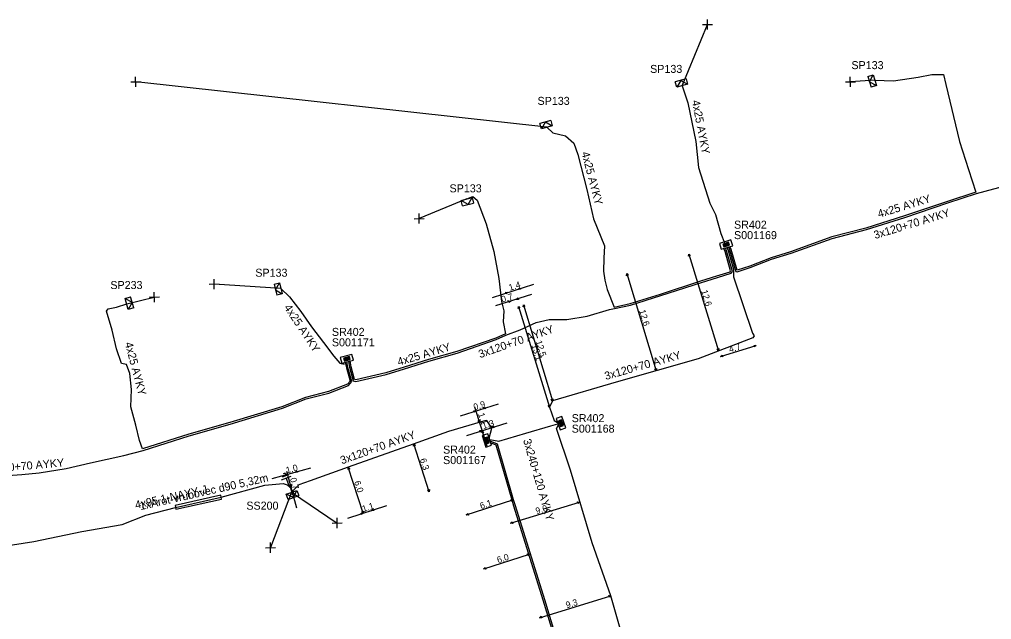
# Model space of a CAD drawing. Extents: x -762504 to -761250, y -1152974 to -1152253.
# Drawn here: x -761447.4 to -761326.7, y -1152367.8 to -1152293.3 of the extents above; entities that cross this region are included whole.
import ezdxf

# ---------------------------------------------------------------- set-up
doc = ezdxf.new("R2010")
doc.units = 0
for name, color, linetype in [('Vrstva 15', 7, 'Continuous'), ('Vrstva 20', 7, 'Continuous'), ('Vrstva 21', 7, 'Continuous'), ('Vrstva 28', 7, 'Continuous'), ('Vrstva 29', 7, 'Continuous'), ('Vrstva 30', 7, 'Continuous'), ('Vrstva 31', 7, 'Continuous'), ('Vrstva 33', 7, 'Continuous'), ('Vrstva 34', 7, 'Continuous'), ('Vrstva 40', 7, 'Continuous'), ('Vrstva 5', 7, 'Continuous'), ('Vrstva 59', 7, 'Continuous'), ('Vrstva 6', 7, 'Continuous')]:
    doc.layers.add(name, color=color, linetype=linetype)

msp = doc.modelspace()

# ---------------------------------------------------------------- linework, layer by layer
at = {"layer": 'Vrstva 15'}
for points in [[(-761414.767, -1152350.065), (-761414.027, -1152349.796)], [(-761414.639, -1152349.683), (-761414.514, -1152349.638)], [(-761414.514, -1152349.638), (-761414.394, -1152349.594)], [(-761414.888, -1152350.439), (-761413.713, -1152350.011)], [(-761413.873, -1152351.4), (-761414.301, -1152350.225)]]:
    msp.add_lwpolyline(points, dxfattribs=at)
at = {"layer": 'Vrstva 20'}
msp.add_lwpolyline([(-761422.44, -1152352.36), (-761428.12, -1152353.64), (-761428.01, -1152354.12), (-761422.33, -1152352.84)], close=True, dxfattribs=at)
at = {"layer": 'Vrstva 28'}
for points in [[(-761359.083, -1152320.657), (-761360.517, -1152321.096)], [(-761359.384, -1152320.947), (-761360.095, -1152321.165)], [(-761359.273, -1152321.308), (-761359.384, -1152320.947)], [(-761358.864, -1152321.375), (-761359.083, -1152320.657)], [(-761360.517, -1152321.096), (-761360.298, -1152321.813)], [(-761360.298, -1152321.813), (-761358.864, -1152321.375)], [(-761360.095, -1152321.165), (-761359.985, -1152321.526)], [(-761359.415, -1152321.006), (-761360.036, -1152321.196)], [(-761360.036, -1152321.196), (-761359.953, -1152321.467)], [(-761359.985, -1152321.526), (-761359.273, -1152321.308)], [(-761359.446, -1152321.065), (-761359.977, -1152321.227)], [(-761359.977, -1152321.227), (-761359.922, -1152321.408)], [(-761359.953, -1152321.467), (-761359.332, -1152321.277)], [(-761359.922, -1152321.408), (-761359.391, -1152321.246)], [(-761359.478, -1152321.124), (-761359.918, -1152321.259)], [(-761359.918, -1152321.259), (-761359.891, -1152321.349)], [(-761359.891, -1152321.349), (-761359.45, -1152321.214)], [(-761359.503, -1152321.181), (-761359.865, -1152321.292)], [(-761359.45, -1152321.214), (-761359.478, -1152321.124)], [(-761359.391, -1152321.246), (-761359.446, -1152321.065)], [(-761359.332, -1152321.277), (-761359.415, -1152321.006)], [(-761406.151, -1152334.865), (-761407.6, -1152335.254)], [(-761407.6, -1152335.254), (-761407.406, -1152335.978)], [(-761406.461, -1152335.144), (-761407.18, -1152335.337)], [(-761407.18, -1152335.337), (-761407.082, -1152335.702)], [(-761406.495, -1152335.202), (-761407.122, -1152335.37)], [(-761407.122, -1152335.37), (-761407.049, -1152335.644)], [(-761406.528, -1152335.26), (-761407.064, -1152335.404)], [(-761407.064, -1152335.404), (-761407.015, -1152335.586)], [(-761406.561, -1152335.318), (-761407.006, -1152335.437)], [(-761406.982, -1152335.528), (-761406.537, -1152335.409)], [(-761406.589, -1152335.374), (-761406.954, -1152335.472)], [(-761406.537, -1152335.409), (-761406.561, -1152335.318)], [(-761406.479, -1152335.442), (-761406.528, -1152335.26)], [(-761406.421, -1152335.476), (-761406.495, -1152335.202)], [(-761406.363, -1152335.509), (-761406.461, -1152335.144)], [(-761405.957, -1152335.59), (-761406.151, -1152334.865)], [(-761407.406, -1152335.978), (-761405.957, -1152335.59)], [(-761407.082, -1152335.702), (-761406.363, -1152335.509)], [(-761407.049, -1152335.644), (-761406.421, -1152335.476)], [(-761407.015, -1152335.586), (-761406.479, -1152335.442)], [(-761407.006, -1152335.437), (-761406.982, -1152335.528)], [(-761380.079, -1152342.586), (-761380.788, -1152342.83)], [(-761379.591, -1152344.004), (-761380.079, -1152342.586)], [(-761380.788, -1152342.83), (-761380.3, -1152344.248)], [(-761380.133, -1152343.01), (-761380.49, -1152343.133)], [(-761380.49, -1152343.133), (-761380.248, -1152343.837)], [(-761380.162, -1152343.07), (-761380.43, -1152343.162)], [(-761380.43, -1152343.162), (-761380.219, -1152343.777)], [(-761380.192, -1152343.13), (-761380.37, -1152343.192)], [(-761380.37, -1152343.192), (-761380.189, -1152343.717)], [(-761380.221, -1152343.19), (-761380.31, -1152343.221)], [(-761380.31, -1152343.221), (-761380.16, -1152343.657)], [(-761380.129, -1152343.602), (-761380.252, -1152343.245)], [(-761380.248, -1152343.837), (-761379.891, -1152343.714)], [(-761380.071, -1152343.626), (-761380.221, -1152343.19)], [(-761380.219, -1152343.777), (-761379.951, -1152343.684)], [(-761380.011, -1152343.655), (-761380.192, -1152343.13)], [(-761380.189, -1152343.717), (-761380.011, -1152343.655)], [(-761379.951, -1152343.684), (-761380.162, -1152343.07)], [(-761380.16, -1152343.657), (-761380.071, -1152343.626)], [(-761379.891, -1152343.714), (-761380.133, -1152343.01)], [(-761389.255, -1152344.734), (-761389.973, -1152344.953)], [(-761389.973, -1152344.953), (-761389.534, -1152346.388)], [(-761388.817, -1152346.168), (-761389.255, -1152344.734)], [(-761380.3, -1152344.248), (-761379.591, -1152344.004)], [(-761389.322, -1152345.143), (-761389.683, -1152345.254)], [(-761389.683, -1152345.254), (-761389.465, -1152345.965)], [(-761389.353, -1152345.202), (-761389.624, -1152345.285)], [(-761389.624, -1152345.285), (-761389.434, -1152345.906)], [(-761389.384, -1152345.261), (-761389.565, -1152345.316)], [(-761389.565, -1152345.316), (-761389.403, -1152345.847)], [(-761389.534, -1152346.388), (-761388.817, -1152346.168)], [(-761389.416, -1152345.32), (-761389.506, -1152345.348)], [(-761389.506, -1152345.348), (-761389.371, -1152345.788)], [(-761389.465, -1152345.965), (-761389.104, -1152345.855)], [(-761389.449, -1152345.373), (-761389.338, -1152345.735)], [(-761389.434, -1152345.906), (-761389.163, -1152345.823)], [(-761389.281, -1152345.761), (-761389.416, -1152345.32)], [(-761389.403, -1152345.847), (-761389.222, -1152345.792)], [(-761389.222, -1152345.792), (-761389.384, -1152345.261)], [(-761389.371, -1152345.788), (-761389.281, -1152345.761)], [(-761389.163, -1152345.823), (-761389.353, -1152345.202)], [(-761389.104, -1152345.855), (-761389.322, -1152345.143)]]:
    msp.add_lwpolyline(points, dxfattribs=at)
at = {"layer": 'Vrstva 31'}
for points in [[(-761342.075, -1152300.333), (-761341.406, -1152300.128), (-761340.997, -1152301.467), (-761341.666, -1152301.671)], [(-761342.075, -1152300.333), (-761341.666, -1152301.671)], [(-761341.871, -1152301.002), (-761341.406, -1152300.128)], [(-761364.642, -1152300.642), (-761365.995, -1152301.004)], [(-761364.642, -1152300.642), (-761364.461, -1152301.318), (-761365.813, -1152301.68), (-761365.995, -1152301.004)], [(-761365.318, -1152300.823), (-761365.813, -1152301.68)], [(-761365.318, -1152300.823), (-761364.461, -1152301.318)], [(-761341.871, -1152301.002), (-761340.997, -1152301.467)], [(-761381.457, -1152305.793), (-761382.803, -1152306.179)], [(-761381.457, -1152305.793), (-761381.264, -1152306.466), (-761382.61, -1152306.852), (-761382.803, -1152306.179)], [(-761382.13, -1152305.986), (-761382.61, -1152306.852)], [(-761382.13, -1152305.986), (-761381.264, -1152306.466)], [(-761392.403, -1152316.41), (-761392.572, -1152315.73), (-761391.213, -1152315.392), (-761391.044, -1152316.071)], [(-761391.723, -1152316.24), (-761392.572, -1152315.73)], [(-761392.403, -1152316.41), (-761391.044, -1152316.071)], [(-761391.723, -1152316.24), (-761391.213, -1152315.392)], [(-761415.811, -1152326.153), (-761415.129, -1152325.995), (-761414.814, -1152327.359), (-761415.496, -1152327.517)], [(-761415.811, -1152326.153), (-761415.496, -1152327.517)], [(-761415.653, -1152326.835), (-761415.129, -1152325.995)], [(-761415.653, -1152326.835), (-761414.814, -1152327.359)], [(-761433.253, -1152329.083), (-761433.926, -1152329.276), (-761434.312, -1152327.93), (-761433.639, -1152327.737)], [(-761433.446, -1152328.41), (-761434.312, -1152327.93)], [(-761433.253, -1152329.083), (-761433.639, -1152327.737)], [(-761433.446, -1152328.41), (-761433.926, -1152329.276)], [(-761414.071, -1152352.899), (-761414.31, -1152352.241), (-761412.995, -1152351.762), (-761412.755, -1152352.42)], [(-761413.413, -1152352.659), (-761414.31, -1152352.241)], [(-761413.413, -1152352.659), (-761412.995, -1152351.762)], [(-761414.071, -1152352.899), (-761412.755, -1152352.42)]]:
    msp.add_lwpolyline(points, dxfattribs=at)
at = {"layer": 'Vrstva 34'}
for points in [[(-761362.625, -1152293.891), (-761361.375, -1152293.869)], [(-761361.989, -1152294.505), (-761362.011, -1152293.255)], [(-761432.989, -1152301.625), (-761433.011, -1152300.375)], [(-761344.239, -1152301.625), (-761344.261, -1152300.375)], [(-761433.625, -1152301.011), (-761432.375, -1152300.989)], [(-761344.875, -1152301.011), (-761343.625, -1152300.989)], [(-761398.435, -1152318.011), (-761397.185, -1152317.989)], [(-761397.799, -1152318.625), (-761397.821, -1152317.375)], [(-761423.239, -1152326.755), (-761423.261, -1152325.505)], [(-761423.875, -1152326.141), (-761422.625, -1152326.119)], [(-761431.315, -1152327.761), (-761430.065, -1152327.739)], [(-761430.679, -1152328.375), (-761430.701, -1152327.125)], [(-761408.615, -1152355.831), (-761407.365, -1152355.809)], [(-761407.979, -1152356.445), (-761408.001, -1152355.195)], [(-761416.259, -1152359.505), (-761416.281, -1152358.255)], [(-761416.895, -1152358.891), (-761415.645, -1152358.869)]]:
    msp.add_lwpolyline(points, dxfattribs=at)
at = {"layer": 'Vrstva 40'}
for points in [[(-761364.331, -1152322.418), (-761364.154, -1152322.622), (-761364.353, -1152322.686)], [(-761372.011, -1152324.838), (-761371.838, -1152325.045), (-761372.038, -1152325.106)], [(-761385.492, -1152326.76), (-761385.288, -1152326.584), (-761385.224, -1152326.783)], [(-761386.778, -1152327.179), (-761386.982, -1152327.356), (-761387.046, -1152327.157)], [(-761385.752, -1152328.04), (-761385.548, -1152327.864), (-761385.483, -1152328.063)], [(-761386.427, -1152328.249), (-761386.631, -1152328.425), (-761386.696, -1152328.226)], [(-761385.481, -1152328.908), (-761385.305, -1152329.112), (-761385.503, -1152329.176)], [(-761384.85, -1152328.708), (-761384.678, -1152328.915), (-761384.877, -1152328.976)], [(-761360.62, -1152334.422), (-761360.796, -1152334.218), (-761360.597, -1152334.154)], [(-761355.938, -1152333.77), (-761356.142, -1152333.946), (-761356.206, -1152333.747)], [(-761360.393, -1152335.151), (-761360.189, -1152334.974), (-761360.124, -1152335.173)], [(-761368.369, -1152336.903), (-761368.542, -1152336.696), (-761368.342, -1152336.634)], [(-761389.873, -1152341.611), (-761389.669, -1152341.434), (-761389.604, -1152341.633)], [(-761381.599, -1152341.432), (-761381.776, -1152341.228), (-761381.577, -1152341.164)], [(-761381.239, -1152340.662), (-761381.412, -1152340.455), (-761381.212, -1152340.394)], [(-761390.747, -1152341.889), (-761390.951, -1152342.065), (-761391.016, -1152341.866)], [(-761390.29, -1152343.323), (-761390.466, -1152343.119), (-761390.267, -1152343.054)], [(-761388.782, -1152343.961), (-761388.578, -1152343.784), (-761388.513, -1152343.983)], [(-761389.988, -1152344.34), (-761390.192, -1152344.516), (-761390.256, -1152344.317)], [(-761389.961, -1152344.358), (-761389.785, -1152344.562), (-761389.983, -1152344.627)], [(-761398.481, -1152345.987), (-761398.305, -1152346.191), (-761398.504, -1152346.256)], [(-761414.127, -1152349.75), (-761414.337, -1152349.919), (-761414.395, -1152349.718)], [(-761413.182, -1152349.49), (-761412.972, -1152349.321), (-761412.914, -1152349.522)], [(-761406.601, -1152348.897), (-761406.424, -1152349.102), (-761406.623, -1152349.166)], [(-761413.699, -1152351.353), (-761413.868, -1152351.143), (-761413.667, -1152351.085)], [(-761413.51, -1152352.038), (-761413.341, -1152352.248), (-761413.542, -1152352.305)], [(-761396.549, -1152351.943), (-761396.726, -1152351.738), (-761396.527, -1152351.674)], [(-761386.168, -1152352.949), (-761386.372, -1152353.125), (-761386.436, -1152352.927)], [(-761377.867, -1152353.21), (-761378.071, -1152353.386), (-761378.136, -1152353.187)], [(-761404.748, -1152354.599), (-761404.952, -1152354.775), (-761405.016, -1152354.577)], [(-761404.749, -1152354.602), (-761404.926, -1152354.398), (-761404.727, -1152354.334)], [(-761403.702, -1152354.261), (-761403.498, -1152354.084), (-761403.434, -1152354.283)], [(-761391.963, -1152354.821), (-761391.758, -1152354.644), (-761391.694, -1152354.843)], [(-761386.452, -1152355.851), (-761386.248, -1152355.674), (-761386.184, -1152355.873)], [(-761384.087, -1152359.69), (-761384.292, -1152359.866), (-761384.356, -1152359.667)], [(-761389.793, -1152361.531), (-761389.588, -1152361.354), (-761389.524, -1152361.553)], [(-761373.978, -1152364.859), (-761374.182, -1152365.036), (-761374.246, -1152364.837)], [(-761382.842, -1152367.58), (-761382.638, -1152367.404), (-761382.573, -1152367.603)]]:
    msp.add_lwpolyline(points, close=True, dxfattribs=at)
for points in [[(-761364.33, -1152322.42), (-761360.62, -1152334.42)], [(-761372.01, -1152324.84), (-761368.37, -1152336.9)], [(-761388.68, -1152327.79), (-761383.58, -1152326.16)], [(-761383.84, -1152327.44), (-761388.34, -1152328.84)], [(-761385.48, -1152328.91), (-761381.6, -1152341.43)], [(-761384.85, -1152328.71), (-761381.24, -1152340.66)], [(-761360.39, -1152335.15), (-761355.94, -1152333.77)], [(-761392.65, -1152342.5), (-761387.96, -1152341)], [(-761389.35, -1152346.27), (-761390.9, -1152341.41)], [(-761391.9, -1152344.93), (-761386.87, -1152343.37)], [(-761396.55, -1152351.94), (-761398.48, -1152345.99)], [(-761416.06, -1152350.28), (-761411.25, -1152348.97)], [(-761412.98, -1152353.97), (-761414.22, -1152349.42)], [(-761404.75, -1152354.6), (-761406.6, -1152348.9)], [(-761391.96, -1152354.82), (-761386.17, -1152352.95)], [(-761386.45, -1152355.85), (-761377.87, -1152353.21)], [(-761406.65, -1152355.22), (-761401.8, -1152353.64)], [(-761389.79, -1152361.53), (-761384.09, -1152359.69)], [(-761382.84, -1152367.58), (-761373.98, -1152364.86)]]:
    msp.add_lwpolyline(points, dxfattribs=at)
at = {"layer": 'Vrstva 5'}
for points in [[(-761341.2, -1152300.8), (-761338.88, -1152300.9), (-761335.82, -1152300.44), (-761334.13, -1152300.1), (-761332.68, -1152300.11), (-761332.41, -1152301.32), (-761330.71, -1152308.4), (-761329.6, -1152311.91), (-761328.66, -1152314.71), (-761332.2, -1152315.86), (-761337.55, -1152317.66), (-761342.33, -1152319.17), (-761346.56, -1152320.26), (-761351.68, -1152322.11), (-761354.1, -1152322.86), (-761356.75, -1152323.91), (-761358.32, -1152324.41), (-761359.06, -1152321.83), (-761359.21, -1152321.45)], [(-761365.14, -1152301.5), (-761364.44, -1152303.61), (-761363.46, -1152308.43), (-761363.12, -1152311.66), (-761361.71, -1152316.09), (-761361, -1152317.5), (-761360.32, -1152319.86), (-761359.89, -1152320.99)], [(-761381.94, -1152306.66), (-761381.21, -1152307.36), (-761379.64, -1152307.7), (-761378.61, -1152308.62), (-761378.09, -1152310.04), (-761376.96, -1152314.37), (-761376.15, -1152318.03), (-761374.8, -1152321.38), (-761374.86, -1152322.92), (-761374.93, -1152324.53), (-761374.74, -1152325.63), (-761374.45, -1152326.8), (-761373.59, -1152328.99), (-761371.61, -1152328.56), (-761367.83, -1152327.38), (-761362.82, -1152325.75), (-761360.82, -1152325.12), (-761359.2, -1152324.6), (-761359.13, -1152324.47), (-761359.82, -1152322.09), (-761359.95, -1152321.73)], [(-761359.39, -1152321.52), (-761359.25, -1152321.9), (-761358.48, -1152324.57), (-761358.31, -1152324.62), (-761356.69, -1152324.09), (-761354.04, -1152323.04), (-761351.62, -1152322.3), (-761346.5, -1152320.46), (-761342.27, -1152319.37), (-761337.49, -1152317.85), (-761332.14, -1152316.05), (-761328.6, -1152314.9), (-761324.75, -1152313.83), (-761321.73, -1152312.99), (-761318.49, -1152312), (-761317.09, -1152311.55), (-761314.13, -1152310.74), (-761310.4, -1152309.51), (-761310.19, -1152308.81), (-761310.75, -1152307.52), (-761310.97, -1152306.6)], [(-761391.89, -1152315.56), (-761391.13, -1152315.27), (-761390.59, -1152315.71), (-761389.5, -1152318.67), (-761388.54, -1152322.07), (-761387.92, -1152325.45), (-761387.56, -1152328.31), (-761387.29, -1152329.46), (-761387.39, -1152330.81), (-761387.1, -1152332.3), (-761388.3, -1152332.85), (-761393.14, -1152334.51), (-761396.65, -1152335.51), (-761399.68, -1152336.47), (-761401.95, -1152337.16), (-761405.66, -1152338.04), (-761405.82, -1152337.99), (-761406.25, -1152336.4), (-761406.39, -1152335.69)], [(-761406.58, -1152335.75), (-761406.44, -1152336.45), (-761405.99, -1152338.15), (-761405.66, -1152338.24), (-761401.89, -1152337.36), (-761399.62, -1152336.66), (-761396.59, -1152335.71), (-761393.08, -1152334.71), (-761388.22, -1152333.03), (-761387.04, -1152332.49), (-761385.26, -1152331.81), (-761383.26, -1152330.92), (-761381.67, -1152330.52), (-761379.47, -1152330.55), (-761376.93, -1152330.12), (-761374.15, -1152329.28), (-761373.53, -1152329.18), (-761371.56, -1152328.76), (-761367.77, -1152327.57), (-761362.76, -1152325.94), (-761360.76, -1152325.31), (-761359.05, -1152324.77), (-761358.89, -1152324.58), (-761359.63, -1152322.02), (-761359.77, -1152321.66)], [(-761359.58, -1152321.59), (-761359.44, -1152321.96), (-761358.77, -1152324.28), (-761358.76, -1152325.22), (-761356.41, -1152332.22), (-761356.21, -1152332.58), (-761356.37, -1152332.81), (-761363.16, -1152335.41), (-761373.34, -1152338.32), (-761381.24, -1152340.66), (-761381.6, -1152341.43), (-761381.05, -1152343.08), (-761380.61, -1152343.34)], [(-761414.97, -1152326.68), (-761413.92, -1152327.7), (-761412.48, -1152329.54), (-761411.16, -1152331.46), (-761409.69, -1152333.39), (-761408.39, -1152335.1), (-761407.66, -1152335.98), (-761407.13, -1152336.09), (-761407.17, -1152335.91)], [(-761406.97, -1152335.87), (-761406.83, -1152336.54), (-761406.39, -1152338.18), (-761406.7, -1152338.59), (-761409.06, -1152339.5), (-761411.9, -1152340.22), (-761414.85, -1152341.38), (-761421.32, -1152343.35), (-761426.42, -1152344.79), (-761432.15, -1152346.62), (-761432.53, -1152345.57), (-761432.99, -1152343.67), (-761433.6, -1152341.4), (-761433.53, -1152339.23), (-761433.73, -1152337.26), (-761434.13, -1152336.13), (-761434.77, -1152336.02), (-761435.4, -1152334.2), (-761435.94, -1152331.87), (-761436.62, -1152329.49), (-761436.41, -1152329.23), (-761435.37, -1152329.02), (-761434.12, -1152328.6)], [(-761450.14, -1152349.98), (-761447.16, -1152349.78), (-761445, -1152349.59), (-761441.65, -1152349.04), (-761438.6, -1152348.33), (-761434.47, -1152347.42), (-761432.09, -1152346.81), (-761426.36, -1152344.99), (-761421.26, -1152343.55), (-761414.79, -1152341.56), (-761411.84, -1152340.41), (-761409, -1152339.69), (-761406.58, -1152338.75), (-761406.17, -1152338.22), (-761406.64, -1152336.49), (-761406.78, -1152335.81)], [(-761389.11, -1152345.26), (-761388.78, -1152344.03), (-761389.4, -1152343.08), (-761389.83, -1152343.15), (-761394.15, -1152344.46), (-761398.56, -1152346.01), (-761406.6, -1152348.9), (-761411.32, -1152350.6), (-761412.74, -1152351.09), (-761413.65, -1152352)], [(-761389.04, -1152345.45), (-761387.89, -1152345.67), (-761384.57, -1152344.65), (-761381.43, -1152343.76), (-761380.57, -1152343.5)], [(-761372.68, -1152369.52), (-761373.98, -1152364.86), (-761376.31, -1152358.28), (-761379, -1152349.26), (-761380.75, -1152344.09), (-761380.51, -1152343.63)], [(-761379.03, -1152375.78), (-761382.2, -1152365.35), (-761385.85, -1152353.67), (-761386.07, -1152352.92), (-761388.07, -1152346.03), (-761388.99, -1152345.64)], [(-761379.23, -1152375.84), (-761382.4, -1152365.41), (-761386.05, -1152353.73), (-761386.27, -1152352.98), (-761388.25, -1152346.15), (-761388.93, -1152345.85)], [(-761451.55, -1152359.02), (-761445.67, -1152358.12), (-761439.7, -1152356.89), (-761434.68, -1152356), (-761431.74, -1152354.83), (-761428.06, -1152353.88), (-761422.38, -1152352.6), (-761416.97, -1152351.1), (-761414.67, -1152350.93), (-761414.2, -1152351.06), (-761413.77, -1152351.45), (-761413.65, -1152352)]]:
    msp.add_lwpolyline(points, dxfattribs=at)
at = {"layer": 'Vrstva 59'}
for points in [[(-761365.14, -1152301.5), (-761362, -1152293.88)], [(-761381.94, -1152306.66), (-761433, -1152301)], [(-761341.2, -1152300.8), (-761344.25, -1152301)], [(-761391.89, -1152315.56), (-761397.81, -1152318)], [(-761414.97, -1152326.68), (-761423.25, -1152326.13)], [(-761434.12, -1152328.6), (-761430.69, -1152327.75)], [(-761413.65, -1152352), (-761416.27, -1152358.88)], [(-761413.65, -1152352), (-761407.99, -1152355.82)]]:
    msp.add_lwpolyline(points, dxfattribs=at)

# ---------------------------------------------------------------- texts
at = {"layer": 'Vrstva 21'}
msp.add_text('1xArot-vrubovec d90 5,32m', height=0.99428, rotation=12.69958, dxfattribs=at).set_placement((-761432.39, -1152354.22))
at = {"layer": 'Vrstva 29'}
for s, p in [('S001169', (-761358.7, -1152320.55)), ('S001171', (-761408.64, -1152333.87)), ('S001168', (-761378.86, -1152344.59)), ('S001167', (-761394.83, -1152348.5))]:
    msp.add_text(s, height=0.9943, dxfattribs=at).set_placement(p)
at = {"layer": 'Vrstva 30'}
for p in [(-761358.7, -1152319.25), (-761408.64, -1152332.57), (-761378.86, -1152343.29), (-761394.83, -1152347.2)]:
    msp.add_text('SR402', height=0.9943, dxfattribs=at).set_placement(p)
at = {"layer": 'Vrstva 33'}
for s, p in [('SP133', (-761369.12, -1152299.9)), ('SP133', (-761344.12, -1152299.43)), ('SP133', (-761383.1, -1152303.87)), ('SP133', (-761394.03, -1152314.74)), ('SP133', (-761418.15, -1152325.22)), ('SP233', (-761436.15, -1152326.75)), ('SS200', (-761419.26, -1152354.16))]:
    msp.add_text(s, height=0.9943, dxfattribs=at).set_placement(p)
at = {"layer": 'Vrstva 40'}
for s, rotation, p in [('1,4', 17.73493, (-761386.54, -1152326.97)), ('12,6', 287.18504, (-761362.79, -1152326.99)), ('0,7', 17.2057, (-761387.48, -1152328.45)), ('12,6', 286.79207, (-761370.5, -1152329.44)), ('13,1', 287.21377, (-761383.86, -1152333.74)), ('12,5', 286.7921, (-761383.35, -1152333.26)), ('4,7', 17.18324, (-761359.21, -1152334.66)), ('0,9', 17.66268, (-761390.92, -1152341.82)), ('1,1', 287.66671, (-761390.5, -1152342.27)), ('1,3', 17.1172, (-761389.83, -1152344.16)), ('1,0', 15.27098, (-761414.23, -1152349.66)), ('6,3', 287.97723, (-761397.73, -1152347.92)), ('0,7', 285.26373, (-761413.86, -1152350.3)), ('6,0', 287.97808, (-761405.89, -1152350.71)), ('1,1', 17.97577, (-761404.75, -1152354.47)), ('6,1', 17.89309, (-761390.11, -1152354.1)), ('9,0', 17.11659, (-761383.21, -1152354.73)), ('6,0', 17.89371, (-761387.99, -1152360.82)), ('9,3', 17.06825, (-761379.46, -1152366.42))]:
    msp.add_text(s, height=0.7954, rotation=rotation, dxfattribs=at).set_placement(p)
at = {"layer": 'Vrstva 6'}
for s, height, rotation, p in [('4x25 AYKY', 0.9943, 280.89873, (-761363.94, -1152303.38)), ('4x25 AYKY', 0.9943, 284.79109, (-761377.66, -1152309.82)), ('4x25 AYKY', 0.9943, 16.93024, (-761340.7, -1152317.91)), ('3x120+70 AYKY', 0.99428, 16.96639, (-761341.18, -1152320.55)), ('4x25 AYKY', 0.9943, 303.55283, (-761414.63, -1152329.05)), ('3x120+70 AYKY', 0.99429, 19.24952, (-761390.24, -1152335.35)), ('4x25 AYKY', 0.9943, 284.79676, (-761434.36, -1152333.48)), ('4x25 AYKY', 0.9943, 16.61244, (-761400.34, -1152336.3)), ('3x120+70 AYKY', 0.99429, 15.95283, (-761374.63, -1152338.06)), ('3x120+70 AYKY', 0.99429, 19.62758, (-761407.39, -1152348.54)), ('3x240+120 AYKY', 0.99428, 286.2439, (-761384.91, -1152345.52)), ('3x120+70 AYKY', 0.99429, 5.07427, (-761451.62, -1152349.65)), ('4x95 1-NAYY-J', 0.99428, 12.69958, (-761432.97, -1152354.08))]:
    msp.add_text(s, height=height, rotation=rotation, dxfattribs=at).set_placement(p)

doc.saveas('drawing.dxf')
